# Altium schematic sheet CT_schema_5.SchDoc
size 293 x 198 mm
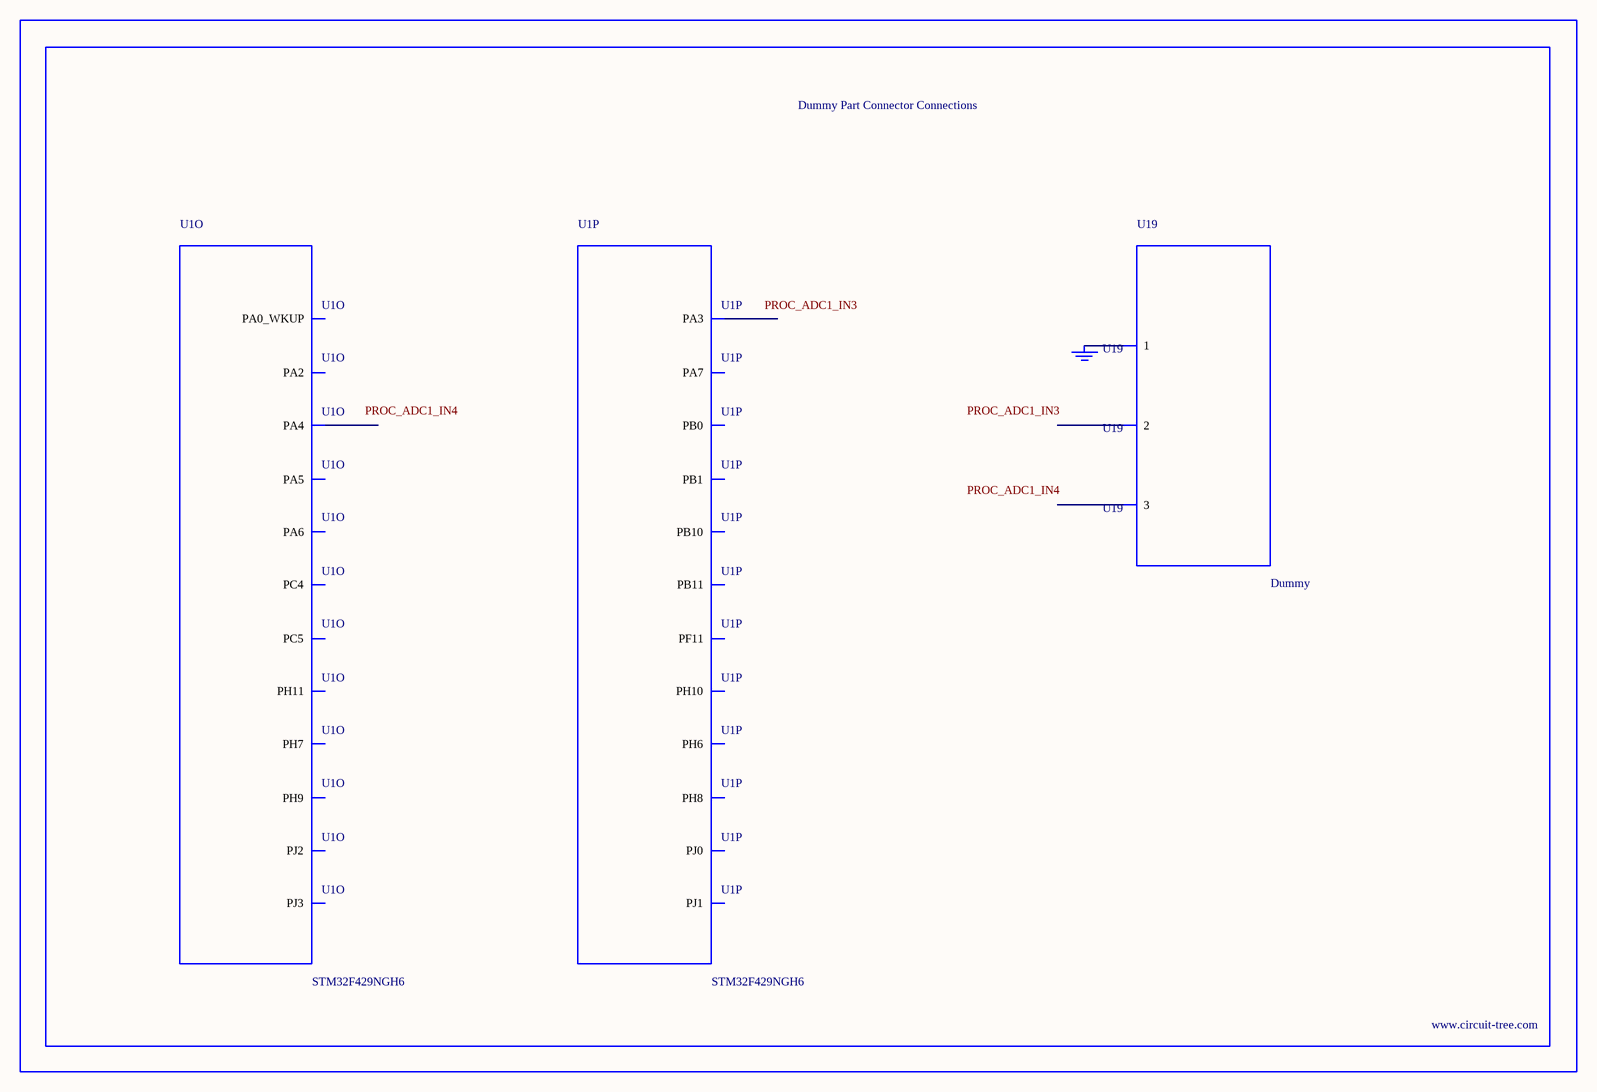
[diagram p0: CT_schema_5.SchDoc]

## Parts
BORDER4  (no value)
GND_INSTANCE_4_0  (no value)
U1  STM32F429NGH6  [TFBGA216]  (parts O,P of 16)
U19  Dummy  [DUMMY_PACKAGE_254]

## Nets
NetGND_INSTANCE_4_0_0: GND_INSTANCE_4_0.0(GND) U19.1

Not connected (* = marked no-connect by the designer): U1 N3(PA0_WKUP) N4(PA4) N5(PC4) N8(PJ3) N13(PH7) N14(PH9) N15(PH11) P2(PA2) P3(PA6) P4(PA5) P5(PC5) P7(PJ2) P8(PF11) P12(PB10) P13(PH6) P14(PH8) P15(PH10) R2(PA3) R3(PA7) R4(PB1) R5(PB0) R6(PJ0) R7(PJ1) R13(PB11); U19 2 3

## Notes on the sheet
- Labels drawn without touching a wire or pin: PROC_ADC1_IN3, PROC_ADC1_IN4

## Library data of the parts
BORDER4 = BORDER_PAGE4
GND_INSTANCE_4_0 = GND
